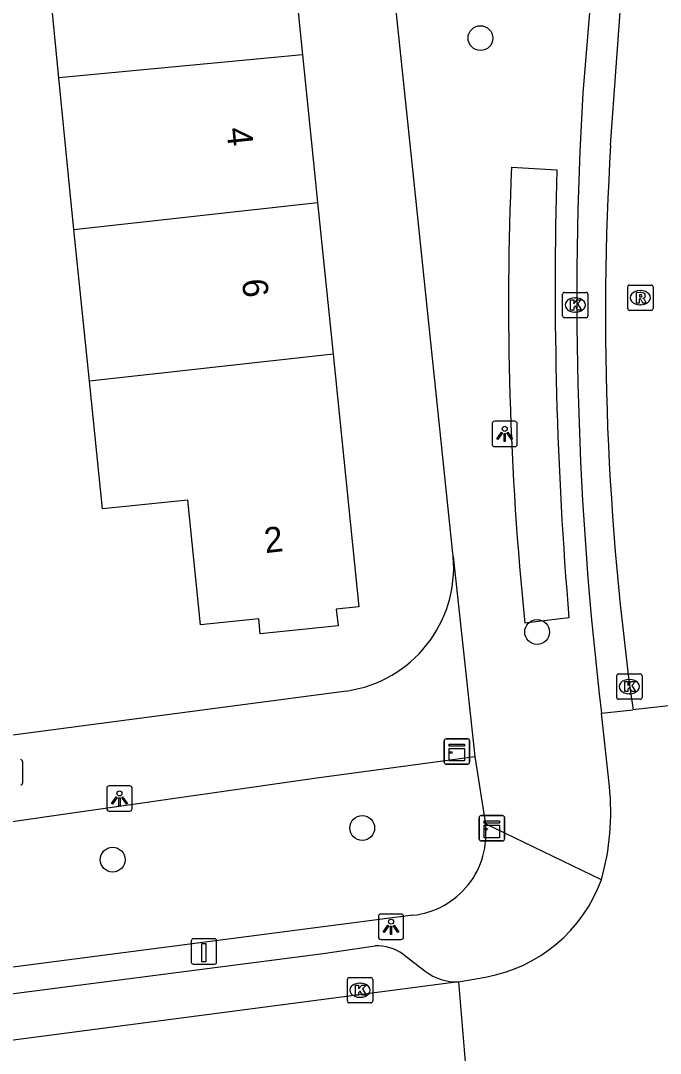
# Model space of a CAD drawing. Extents: x 162074 to 163034, y 381824 to 382557.
# Drawn here: x 162446.55 to 162471.78, y 382465.37 to 382506.13 of the extents above; entities that cross this region are included whole.
import ezdxf

# ---------------------------------------------------------------- set-up
doc = ezdxf.new("R2010")
doc.units = 0
for name, color, linetype in [('IMGEO_Boom', 7, 'Continuous'), ('IMGEO_Brandkraan', 7, 'Continuous'), ('IMGEO_Fietspad_gesloten', 7, 'Continuous'), ('IMGEO_Kast', 7, 'Continuous'), ('IMGEO_Kolk', 7, 'Continuous'), ('IMGEO_Laadpaal', 7, 'Continuous'), ('IMGEO_Lichtpunt', 7, 'Continuous'), ('IMGEO_Pand', 7, 'Continuous'), ('IMGEO_Pand_nummerreeks', 7, 'Continuous'), ('IMGEO_Rijbaan_lokaal_open', 7, 'Continuous'), ('IMGEO_Rioolput', 7, 'Continuous'), ('IMGEO_Voetpad_open', 7, 'Continuous')]:
    doc.layers.add(name, color=color, linetype=linetype)

msp = doc.modelspace()

# ---------------------------------------------------------------- linework, layer by layer
at = {"layer": 'IMGEO_Boom'}
for centre in [(162464.685, 382505.441), (162466.92, 382482), (162460.023, 382474.265), (162450.182, 382473.015)]:
    msp.add_circle(centre, 0.489, dxfattribs=at)
at = {"layer": 'IMGEO_Brandkraan'}
msp.add_line((162446.625, 382476.891), (162446.625, 382476.039), dxfattribs=at)
msp.add_lwpolyline([(162446.625, 382476.891), (162446.625, 382476.039)], dxfattribs=at)
for centre, start, end in [((162446.549, 382476.889), 1.552, 88.448), ((162446.549, 382476.889), 1.552, 88.448), ((162446.549, 382476.041), 271.552, 358.448), ((162446.549, 382476.041), 271.552, 358.448)]:
    msp.add_arc(centre, 0.0765, start, end, dxfattribs=at)
at = {"layer": 'IMGEO_Fietspad_gesloten'}
msp.add_lwpolyline([(162469.075, 382507.575), (162468.727, 382503.267)], dxfattribs=at)
msp.add_arc((162606.343, 382495.142), 137.856, 176.62101, 186.80672, dxfattribs=at)
at = {"layer": 'IMGEO_Kast'}
for p, q in [((162463.256, 382476.86), (162463.256, 382477.701)), ((162463.256, 382477.701), (162463.256, 382476.86)), ((162463.331, 382477.785), (162464.172, 382477.785)), ((162464.172, 382477.785), (162463.331, 382477.785)), ((162464.256, 382477.71), (162464.256, 382476.869)), ((162464.256, 382476.869), (162464.256, 382477.71)), ((162464.181, 382476.785), (162463.34, 382476.785)), ((162463.34, 382476.785), (162464.181, 382476.785)), ((162464.636, 382473.831), (162464.636, 382474.672)), ((162464.636, 382474.672), (162464.636, 382473.831)), ((162464.711, 382474.756), (162465.552, 382474.756)), ((162465.552, 382474.756), (162464.711, 382474.756)), ((162465.636, 382474.681), (162465.636, 382473.84)), ((162465.636, 382473.84), (162465.636, 382474.681)), ((162465.561, 382473.756), (162464.72, 382473.756)), ((162464.72, 382473.756), (162465.561, 382473.756))]:
    msp.add_line(p, q, dxfattribs=at)
for points in [[(162463.451, 382477.575), (162464.051, 382477.575), (162464.051, 382477.49), (162463.451, 382477.49), (162463.451, 382477.575)], [(162463.451, 382477.4), (162464.051, 382477.4), (162464.051, 382476.911), (162463.451, 382476.911), (162463.451, 382477.4)], [(162464.831, 382474.546), (162465.431, 382474.546), (162465.431, 382474.461), (162464.831, 382474.461), (162464.831, 382474.546)], [(162464.831, 382474.371), (162465.431, 382474.371), (162465.431, 382473.882), (162464.831, 382473.882), (162464.831, 382474.371)]]:
    msp.add_lwpolyline(points, dxfattribs=at)
for centre in [(162463.535, 382477.249), (162464.915, 382474.22)]:
    msp.add_circle(centre, 0.0377, dxfattribs=at)
for centre, start, end in [((162463.334, 382477.707), 92.4484, 184.2845), ((162463.334, 382477.707), 92.4484, 184.2845), ((162464.178, 382477.707), 2.4484, 94.2845), ((162464.178, 382477.707), 2.4484, 94.2845), ((162463.334, 382476.863), 182.4484, 274.2845), ((162463.334, 382476.863), 182.4484, 274.2845), ((162464.178, 382476.863), 272.4484, 4.2845), ((162464.178, 382476.863), 272.4484, 4.2845), ((162464.714, 382474.678), 92.4484, 184.2845), ((162464.714, 382474.678), 92.4484, 184.2845), ((162465.558, 382474.678), 2.4484, 94.2845), ((162465.558, 382474.678), 2.4484, 94.2845), ((162464.714, 382473.834), 182.4484, 274.2845), ((162464.714, 382473.834), 182.4484, 274.2845), ((162465.558, 382473.834), 272.4484, 4.2845), ((162465.558, 382473.834), 272.4484, 4.2845)]:
    msp.add_arc(centre, 0.0779, start, end, dxfattribs=at)
at = {"layer": 'IMGEO_Kolk'}
for p, q in [((162467.997, 382495.407), (162468.849, 382495.407)), ((162467.922, 382494.481), (162467.922, 382495.333)), ((162468.41, 382495.187), (162468.435, 382495.187)), ((162468.923, 382495.333), (162468.923, 382494.481)), ((162468.433, 382494.627), (162468.408, 382494.627)), ((162468.849, 382494.407), (162467.997, 382494.407)), ((162470.135, 382480.347), (162470.987, 382480.347)), ((162470.06, 382479.421), (162470.06, 382480.273)), ((162470.548, 382480.127), (162470.573, 382480.127)), ((162471.061, 382480.273), (162471.061, 382479.421)), ((162470.571, 382479.567), (162470.546, 382479.567)), ((162470.987, 382479.347), (162470.135, 382479.347)), ((162459.436, 382467.438), (162459.436, 382468.29)), ((162459.511, 382468.364), (162460.363, 382468.364)), ((162459.924, 382468.144), (162459.949, 382468.144)), ((162460.437, 382468.29), (162460.437, 382467.438)), ((162460.363, 382467.364), (162459.511, 382467.364)), ((162459.947, 382467.584), (162459.922, 382467.584))]:
    msp.add_line(p, q, dxfattribs=at)
for points in [[(162467.997, 382495.407), (162468.849, 382495.407)], [(162467.922, 382494.481), (162467.922, 382495.333)], [(162468.243, 382495.107), (162468.366, 382495.107), (162468.366, 382494.956), (162468.496, 382495.107), (162468.66, 382495.107), (162468.514, 382494.956), (162468.667, 382494.707), (162468.515, 382494.707), (162468.43, 382494.871), (162468.366, 382494.804), (162468.366, 382494.707), (162468.243, 382494.707), (162468.243, 382495.107)], [(162468.923, 382495.333), (162468.923, 382494.481)], [(162468.849, 382494.407), (162467.997, 382494.407)], [(162470.135, 382480.347), (162470.987, 382480.347)], [(162470.06, 382479.421), (162470.06, 382480.273)], [(162470.381, 382480.047), (162470.504, 382480.047), (162470.504, 382479.896), (162470.634, 382480.047), (162470.798, 382480.047), (162470.652, 382479.896), (162470.805, 382479.647), (162470.653, 382479.647), (162470.568, 382479.811), (162470.504, 382479.744), (162470.504, 382479.647), (162470.381, 382479.647), (162470.381, 382480.047)], [(162471.061, 382480.273), (162471.061, 382479.421)], [(162470.987, 382479.347), (162470.135, 382479.347)], [(162459.436, 382467.438), (162459.436, 382468.29)], [(162459.511, 382468.364), (162460.363, 382468.364)], [(162460.437, 382468.29), (162460.437, 382467.438)], [(162459.757, 382468.064), (162459.88, 382468.064), (162459.88, 382467.913), (162460.01, 382468.064), (162460.174, 382468.064), (162460.028, 382467.913), (162460.181, 382467.664), (162460.029, 382467.664), (162459.944, 382467.828), (162459.88, 382467.761), (162459.88, 382467.664), (162459.757, 382467.664), (162459.757, 382468.064)], [(162460.363, 382467.364), (162459.511, 382467.364)]]:
    msp.add_lwpolyline(points, dxfattribs=at)
for centre, start, end in [((162467.999, 382495.331), 91.552, 178.448), ((162467.999, 382495.331), 91.552, 178.448), ((162468.847, 382495.331), 1.552, 88.448), ((162468.847, 382495.331), 1.552, 88.448), ((162467.999, 382494.483), 181.552, 268.448), ((162467.999, 382494.483), 181.552, 268.448), ((162468.847, 382494.483), 271.552, 358.448), ((162468.847, 382494.483), 271.552, 358.448), ((162470.137, 382480.271), 91.552, 178.448), ((162470.137, 382480.271), 91.552, 178.448), ((162470.985, 382480.271), 1.552, 88.448), ((162470.985, 382480.271), 1.552, 88.448), ((162470.137, 382479.423), 181.552, 268.448), ((162470.137, 382479.423), 181.552, 268.448), ((162470.985, 382479.423), 271.552, 358.448), ((162470.985, 382479.423), 271.552, 358.448), ((162459.513, 382468.288), 91.552, 178.448), ((162459.513, 382468.288), 91.552, 178.448), ((162460.361, 382468.288), 1.552, 88.448), ((162460.361, 382468.288), 1.552, 88.448), ((162459.513, 382467.44), 181.552, 268.448), ((162459.513, 382467.44), 181.552, 268.448), ((162460.361, 382467.44), 271.552, 358.448), ((162460.361, 382467.44), 271.552, 358.448)]:
    msp.add_arc(centre, 0.0765, start, end, dxfattribs=at)
for centre, major_axis, ratio, start_param, end_param in [((162468.409, 382494.907), (-0.387, 0.002), 0.722429, 4.712389, 7.853982), ((162468.434, 382494.907), (-0.39, 0.002), 0.717154, 1.570796, 4.712389), ((162470.547, 382479.847), (-0.387, 0.002), 0.722429, 4.712389, 7.853982), ((162470.572, 382479.847), (-0.39, 0.002), 0.717154, 1.570796, 4.712389), ((162459.923, 382467.864), (-0.387, 0.002), 0.722429, 4.712389, 7.853982), ((162459.948, 382467.864), (-0.39, 0.002), 0.717154, 1.570796, 4.712389)]:
    msp.add_ellipse(centre, major_axis=major_axis, ratio=ratio, start_param=start_param, end_param=end_param, dxfattribs=at)
at = {"layer": 'IMGEO_Laadpaal'}
for p, q in [((162453.28, 382469.813), (162453.28, 382468.972)), ((162453.28, 382469.813), (162453.28, 382468.972)), ((162454.196, 382469.897), (162453.355, 382469.897)), ((162454.196, 382469.897), (162453.355, 382469.897)), ((162454.28, 382468.981), (162454.28, 382469.822)), ((162454.28, 382468.981), (162454.28, 382469.822)), ((162453.364, 382468.897), (162454.205, 382468.897)), ((162453.364, 382468.897), (162454.205, 382468.897))]:
    msp.add_line(p, q, dxfattribs=at)
msp.add_lwpolyline([(162453.695, 382469.71), (162453.855, 382469.71), (162453.855, 382468.977), (162453.695, 382468.977), (162453.695, 382469.71)], dxfattribs=at)
for centre, start, end in [((162453.358, 382469.819), 92.4484, 184.2845), ((162453.358, 382469.819), 92.4484, 184.2845), ((162454.202, 382469.819), 2.4484, 94.2845), ((162454.202, 382469.819), 2.4484, 94.2845), ((162453.358, 382468.975), 182.4484, 274.2845), ((162453.358, 382468.975), 182.4484, 274.2845), ((162454.202, 382468.975), 272.4484, 4.2845), ((162454.202, 382468.975), 272.4484, 4.2845)]:
    msp.add_arc(centre, 0.0779, start, end, dxfattribs=at)
at = {"layer": 'IMGEO_Lichtpunt'}
for p, q in [((162465.142, 382490.223), (162465.142, 382489.416)), ((162465.142, 382490.223), (162465.142, 382489.416)), ((162466.044, 382490.318), (162465.236, 382490.318)), ((162466.044, 382490.318), (162465.236, 382490.318)), ((162466.138, 382489.416), (162466.138, 382490.223)), ((162466.138, 382489.416), (162466.138, 382490.223)), ((162465.236, 382489.322), (162466.044, 382489.322)), ((162465.236, 382489.322), (162466.044, 382489.322)), ((162449.949, 382475.834), (162449.949, 382475.027)), ((162449.949, 382475.834), (162449.949, 382475.027)), ((162450.851, 382475.929), (162450.043, 382475.929)), ((162450.851, 382475.929), (162450.043, 382475.929)), ((162450.945, 382475.027), (162450.945, 382475.834)), ((162450.945, 382475.027), (162450.945, 382475.834)), ((162450.043, 382474.933), (162450.851, 382474.933)), ((162450.043, 382474.933), (162450.851, 382474.933)), ((162460.66, 382470.771), (162460.66, 382469.964)), ((162460.66, 382470.771), (162460.66, 382469.964)), ((162461.562, 382470.866), (162460.754, 382470.866)), ((162461.562, 382470.866), (162460.754, 382470.866)), ((162461.656, 382469.964), (162461.656, 382470.771)), ((162461.656, 382469.964), (162461.656, 382470.771)), ((162460.754, 382469.87), (162461.562, 382469.87)), ((162460.754, 382469.87), (162461.562, 382469.87))]:
    msp.add_line(p, q, dxfattribs=at)
for points in [[(162465.516, 382489.887), (162465.555, 382489.859), (162465.367, 382489.597), (162465.329, 382489.624), (162465.516, 382489.887)], [(162465.618, 382489.839), (162465.665, 382489.839), (162465.665, 382489.517), (162465.618, 382489.517), (162465.618, 382489.839)], [(162465.728, 382489.859), (162465.766, 382489.886), (162465.953, 382489.624), (162465.914, 382489.596), (162465.728, 382489.859)], [(162450.323, 382475.498), (162450.362, 382475.47), (162450.174, 382475.208), (162450.136, 382475.235), (162450.323, 382475.498)], [(162450.425, 382475.45), (162450.472, 382475.45), (162450.472, 382475.128), (162450.425, 382475.128), (162450.425, 382475.45)], [(162450.535, 382475.47), (162450.573, 382475.497), (162450.76, 382475.235), (162450.721, 382475.207), (162450.535, 382475.47)], [(162461.034, 382470.435), (162461.073, 382470.407), (162460.885, 382470.145), (162460.847, 382470.172), (162461.034, 382470.435)], [(162461.136, 382470.387), (162461.183, 382470.387), (162461.183, 382470.065), (162461.136, 382470.065), (162461.136, 382470.387)], [(162461.246, 382470.407), (162461.284, 382470.434), (162461.471, 382470.172), (162461.432, 382470.144), (162461.246, 382470.407)]]:
    msp.add_lwpolyline(points, dxfattribs=at)
for centre in [(162465.641, 382490.021), (162450.448, 382475.632), (162461.159, 382470.569)]:
    msp.add_circle(centre, 0.0994, dxfattribs=at)
for centre, start, end in [((162465.236, 382490.223), 90, 180), ((162465.236, 382490.223), 90, 180), ((162466.044, 382490.223), 0, 90), ((162466.044, 382490.223), 0, 90), ((162465.236, 382489.416), 180, 270), ((162465.236, 382489.416), 180, 270), ((162466.044, 382489.416), 270, 0), ((162466.044, 382489.416), 270, 360), ((162450.043, 382475.834), 90, 180), ((162450.043, 382475.834), 90, 180), ((162450.851, 382475.834), 0, 90), ((162450.851, 382475.834), 0, 90), ((162450.043, 382475.027), 180, 270), ((162450.043, 382475.027), 180, 270), ((162450.851, 382475.027), 270, 0), ((162450.851, 382475.027), 270, 360), ((162460.754, 382470.771), 90, 180), ((162460.754, 382470.771), 90, 180), ((162461.562, 382470.771), 0, 90), ((162461.562, 382470.771), 0, 90), ((162460.754, 382469.964), 180, 270), ((162460.754, 382469.964), 180, 270), ((162461.562, 382469.964), 270, 0), ((162461.562, 382469.964), 270, 360)]:
    msp.add_arc(centre, 0.0946, start, end, dxfattribs=at)
at = {"layer": 'IMGEO_Pand'}
for points in [[(162448.055, 382503.871), (162447.12, 382513.456), (162450.721, 382513.832), (162451.095, 382510.257), (162457.05, 382510.88), (162457.67, 382504.78)], [(162457.67, 382504.78), (162448.055, 382503.871)], [(162457.67, 382504.78), (162458.156, 382500), (162458.262, 382498.952)], [(162448.649, 382497.891), (162448.432, 382500), (162448.055, 382503.871)], [(162448.649, 382497.891), (162458.262, 382498.952)], [(162458.262, 382498.952), (162458.871, 382492.963)], [(162449.264, 382491.902), (162448.649, 382497.891)], [(162458.871, 382492.963), (162459.884, 382482.995), (162459, 382482.904), (162459.069, 382482.24), (162456.001, 382481.925), (162455.94, 382482.52), (162453.65, 382482.285), (162453.145, 382487.206), (162449.782, 382486.86), (162449.264, 382491.902)], [(162458.871, 382492.963), (162449.264, 382491.902)]]:
    msp.add_lwpolyline(points, dxfattribs=at)
at = {"layer": 'IMGEO_Rijbaan_lokaal_open'}
for points in [[(162469.82, 382501.219), (162470.265, 382507.391)], [(162474.121, 382479.316), (162470.702, 382478.932)], [(162469.459, 382478.803), (162470.702, 382478.932)], [(162469.771, 382475.907), (162469.459, 382478.803)], [(162463.823, 382468.189), (162354.468, 382453.854)], [(162463.823, 382468.189), (162464.887, 382468.381)], [(162463.823, 382468.189), (162464.101, 382464.878)]]:
    msp.add_lwpolyline(points, dxfattribs=at)
for centre, radius, start, end in [((162581.05, 382494.46), 111.435, 176.52259, 188.00996), ((162459.993, 382474.889), 9.831, 344.2548, 5.9452), ((162463.83, 382474.275), 5.988, 280.163, 339.9398)]:
    msp.add_arc(centre, radius, start, end, dxfattribs=at)
at = {"layer": 'IMGEO_Rioolput'}
for p, q in [((162470.492, 382494.769), (162470.492, 382495.621)), ((162470.567, 382495.695), (162471.419, 382495.695)), ((162470.98, 382495.475), (162471.005, 382495.475)), ((162471.493, 382495.621), (162471.493, 382494.769)), ((162471.419, 382494.695), (162470.567, 382494.695)), ((162471.003, 382494.915), (162470.978, 382494.915))]:
    msp.add_line(p, q, dxfattribs=at)
for points in [[(162470.492, 382494.769), (162470.492, 382495.621)], [(162470.567, 382495.695), (162471.419, 382495.695)], [(162471.081, 382495.393), (162470.829, 382495.395), (162470.829, 382494.995)], [(162471.493, 382495.621), (162471.493, 382494.769)], [(162470.829, 382494.995), (162470.953, 382494.995), (162470.953, 382495.157), (162470.964, 382495.157)], [(162471.007, 382495.314), (162470.953, 382495.314), (162470.953, 382495.233)], [(162470.953, 382495.233), (162471.005, 382495.233)], [(162471.011, 382495.128), (162471.082, 382494.995), (162471.222, 382494.995), (162471.157, 382495.121)], [(162471.419, 382494.695), (162470.567, 382494.695)]]:
    msp.add_lwpolyline(points, dxfattribs=at)
for centre, radius, start, end in [((162470.569, 382495.619), 0.0765, 91.552, 178.448), ((162470.569, 382495.619), 0.0765, 91.552, 178.448), ((162471.08, 382495.283), 0.109, 350.3612, 89.416), ((162471.417, 382495.619), 0.0765, 1.552, 88.448), ((162471.417, 382495.619), 0.0765, 1.552, 88.448), ((162470.963, 382495.104), 0.0533, 26.0293, 88.6989), ((162470.989, 382495.422), 0.19, 274.7715, 282.9687), ((162471.013, 382495.218), 0.0964, 77.0061, 93.1865), ((162471.027, 382495.275), 0.0378, 276.6634, 79.6772), ((162471.078, 382495.283), 0.112, 277.5842, 350.9817), ((162471.062, 382495.068), 0.108, 29.5134, 73.7905), ((162470.569, 382494.771), 0.0765, 181.552, 268.448), ((162470.569, 382494.771), 0.0765, 181.552, 268.448), ((162471.417, 382494.771), 0.0765, 271.552, 358.448), ((162471.417, 382494.771), 0.0765, 271.552, 358.448)]:
    msp.add_arc(centre, radius, start, end, dxfattribs=at)
for centre, major_axis, ratio, start_param, end_param in [((162470.979, 382495.195), (-0.387, 0.002), 0.722429, 4.712389, 7.853982), ((162471.004, 382495.195), (-0.39, 0.002), 0.717154, 1.570796, 4.712389)]:
    msp.add_ellipse(centre, major_axis=major_axis, ratio=ratio, start_param=start_param, end_param=end_param, dxfattribs=at)
at = {"layer": 'IMGEO_Voetpad_open'}
for points in [[(162463.612, 382484.979), (162462.041, 382500), (162461.042, 382509.55)], [(162465.909, 382500.345), (162467.702, 382500.241)], [(162463.612, 382484.979), (162464.468, 382477.086)], [(162468.175, 382482.555), (162466.433, 382482.345)], [(162442.944, 382477.513), (162459.406, 382479.673)], [(162440.79, 382473.744), (162458.233, 382476.248), (162464.468, 382477.086)], [(162464.468, 382477.086), (162464.792, 382474.99), (162464.88, 382474.427)], [(162469.455, 382472.221), (162464.88, 382474.427)], [(162462.024, 382470.821), (162441.489, 382468.16), (162440.79, 382473.744)], [(162443.118, 382467.325), (162458.485, 382469.312), (162460.531, 382469.62)], [(162461.636, 382469.284), (162462.511, 382468.611)]]:
    msp.add_lwpolyline(points, dxfattribs=at)
for centre, radius, start, end in [((162591.401, 382494.991), 125.606, 177.55682, 185.77812), ((162623.893, 382495.569), 156.261, 178.28664, 184.7773), ((162458.7, 382484.552), 4.93, 278.23, 4.9632), ((162461.669, 382474.036), 3.234, 276.2945, 6.9461), ((162460.58, 382467.796), 1.824, 54.6318, 91.5421), ((162463.772, 382470.281), 2.093, 232.9473, 271.3923)]:
    msp.add_arc(centre, radius, start, end, dxfattribs=at)

# ---------------------------------------------------------------- texts
at = {"layer": 'IMGEO_Pand_nummerreeks'}
for s, rotation, p in [('4', 275.8042, (162454.668, 382501.877)), ('6', 275.8023, (162455.276, 382495.901)), ('2', 6.4975, (162456.207, 382485.112))]:
    msp.add_text(s, height=1, rotation=rotation, dxfattribs=at).set_placement(p)

doc.saveas('drawing.dxf')
